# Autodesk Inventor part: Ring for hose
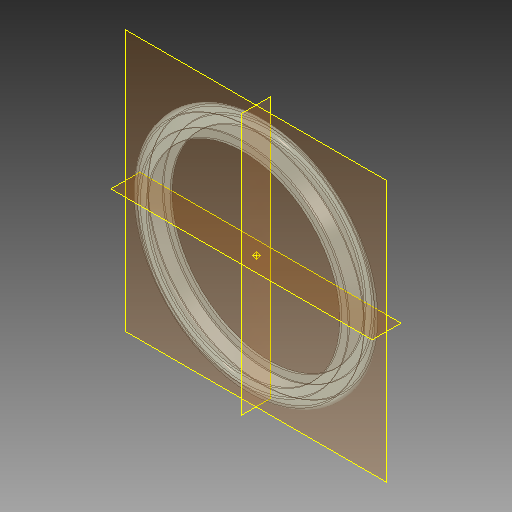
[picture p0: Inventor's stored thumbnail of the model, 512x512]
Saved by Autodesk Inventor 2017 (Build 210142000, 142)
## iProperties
Created: 2020-03
Part Number: Ring for hose
Material: Polycarbonate, Clear
Document SubType Name: Modeling
Designer: user
Density: 1.2 g/cm^3
Appearance: Polycarbonate - Clear
Mass: 0.157757 g
Surface Area: 10.8875 cm^2
Volume: 0.131464 cm^3
Author: user
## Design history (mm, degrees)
sketch "Sketch1"
  geometry: L1 (12.7, 1.584)-(13.867, 0.845); L2 (13.867, -0.845)-(12.711, -1.577); L3 (0, 0)-(1.052, 0); L4 (12.7, 1.584)-(11.7, 1.584); L5 (12.711, -1.577)-(11.711, -1.577); L6 (11.711, -1.327)-(12.639, -1.327); L7 (12.639, -1.327)-(13.733, -0.634); L8 (13.733, 0.634)-(12.627, 1.334); L9 (12.627, 1.334)-(11.7, 1.334); L10 (11.7, 1.584)-(11.7, 1.334); L11 (11.711, -1.327)-(11.711, -1.577); L12 (0, -2.209)-(0, 2.216) reference; A1 r 1 centre (13.332, 0) between (13.867, -0.845) and (13.867, 0.845); A2 r 0.75 centre (13.332, 0) between (13.733, -0.634) and (13.733, 0.634); 1 further point
  constraints: 22 end point, 4 point on circle, 3 horizontal, 2 centre point, 2 point on line, 2 tangent, 1 parallel, 1 vertical, 5 other
  dimensions: "d1" = 3.16094 distance of L2.end L1.start; "d2" = 12.7 horizontal distance of L3.start L1.start; "d3" = 2.5 horizontal distance of L1.start point (15.2, 0); "d4" = 1 radius of A1; "d5" = 1 distance of L1.start L4.end; "d6" = 1 distance of L2.end L5.end; "d8" = 0.25 distance between parallel lines of L1 L8
revolve "Revolution1" sketch "Sketch1" stored, may be unused: angle "d9" = 90 deg
body "Solid1"
